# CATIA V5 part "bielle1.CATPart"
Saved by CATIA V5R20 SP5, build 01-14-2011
Part number: bielle1
Bounding box of the stored display mesh (mm): x -10 to 20, y 20.679 to 162.215, z 22.096 to 99.293
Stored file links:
  F:\iao fini\bielle1.CATPart
  F:\iao fini\iao-finipbgliss.CATProduct
  F:\iao fini\bati.CATPart
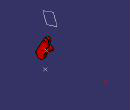
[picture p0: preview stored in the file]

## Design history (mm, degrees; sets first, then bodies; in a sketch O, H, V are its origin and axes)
Set1
  Sketch1 on Plane1, origin (0, 0, 0), H (0, 1, 0), V (0, 0, 1)
    circle A1 centre (29.362, 59.687) radius 8.7156
    point P1 (29.362, 59.687)
    reference projected point E1 (29.362, 59.687) from Point1
    point P2 (49.1286, 45.1699)
    circle A2 centre (26.8771, 22.0963) radius 2.902
    point P3 (26.8771, 22.0963)
    reference projected point E2 (26.8771, 22.0963) from Point2
    circle A3 centre (26.8771, 22.0963) radius 24.695
    point P4 (26.8771, 22.0963)
    reference projected point E3 (26.8771, 22.0963) from Point2
    line L1 (5.2533, 34.0233) -> (21.7303, 63.8964)
    line L2 (21.7303, 63.8964) -> (5.2533, 34.0233)
    radius A2 = 2.902
    coincidence: P1 E1, P3 E2, P4 E3
    tangency: L1 A1, A1 L2, A3 L2, L1 A3
Set2
  Plane1 "plan profil": linked copy from another document
  Point1 "A": linked copy from another document
  Point2 "B": linked copy from another document
  Point3 "C": linked copy from another document
Body1 (main body)
  Pad1: profile Sketch1, direction (1, 0, 0), length 15, opposite side length -10
  Sketch2 on end face of Pad1, origin (15, 0, 0), H (0, 1, 0), V (0, 0, 1)
    circle A1 centre (29.362, 59.687) radius 5.329
    point P1 (29.362, 59.687)
    reference projected point E1 (29.362, 59.687) from Point1
    reference projected point E2 (29.362, 59.687) from Point1
    distance E2 A1 = 5.329
    coincidence: P1 E1
  Pad2: profile Sketch2, direction (1, 0, 0), length 0, opposite side length 25
  Sketch3 on Plane1, origin (0, 0, 0), H (0, 1, 0), V (0, 0, 1)
    circle A1 centre (44.192, 94.318) radius 2.902
    point P1 (44.192, 94.318)
    reference projected point E1 (44.192, 94.318) from Point2
    radius A1 = 2.902
    coincidence: E1 P1
  Pad3: profile Sketch3, direction (1, 0, 0), length 20, opposite side length -10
